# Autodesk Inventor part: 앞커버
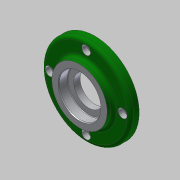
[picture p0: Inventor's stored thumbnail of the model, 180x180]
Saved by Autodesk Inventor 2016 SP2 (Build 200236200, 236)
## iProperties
Created: 2019-01
Part Number: 앞커버
Material: 알루미늄 6061
Document SubType Name: Modeling
Designer: mduedu
Density: 1 g/cm^3
Appearance: 알루미늄 - 평지
Author: mduedu
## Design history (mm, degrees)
sketch "스케치1"
  geometry: L1 (0, 0)-(6, 0); L2 (6, 0)-(6, 25); L3 (6, 25)-(0, 25); L4 (0, 25)-(0, 0); L5 (6, 0)-(14, 0); L6 (14, 0)-(14, 40); L7 (14, 40)-(6, 40); L8 (6, 40)-(6, 0); L9 (14, 0)-(19, 0); L10 (19, 0)-(19, 26); L11 (19, 26)-(14, 26); L12 (14, 26)-(14, 0)
  constraints: 24 end point, 6 parallel, 3 horizontal, 3 perpendicular
  dimensions: "d6" = 80 diameter of L7 L5; "d8" = 50 diameter of L3 L1; "d9" = 52 diameter of L11 L9; "d10" = 5 distance of L10.end L11.end; "d11" = 6 distance of L2.end L3.end; "d12" = 19 distance between parallel lines of L4 L10; "d13" = 8 distance of L6.end L7.end (derived)
revolve "회전1" sketch "스케치1" stored, may be unused: angle "d5" = 90 deg
sketch "스케치2"
  geometry: C1 r 13.5 at (0, 0); 1 further point
  constraints: 1 centre point, 1 coincident
  dimensions: "d14" = 27 diameter of C1
extrude "돌출1" cut sketch "스케치2" stored distance "d15" = 10; taper "d16" = 0 deg
sketch "스케치3" dims "d17" = 66
  geometry: 6 further points
  constraints: 2 vertical alignment, 1 coincident, 7 other
  dimensions: "d20" = 360 deg dimension on point (0, 0) point (0, 33) (derived)
sketch "스케치4"
  geometry: 4 further points
  constraints: 4 other
hole "구멍1" sketch "스케치4" at (-33, 0), (0, -33), (33, 0), (0, 33) diameter "d22" = 4.5; stored, may be unused: countersink angle "d26" = 90 deg, drill point angle "d28" = 0 deg; dims "d23" = 6, "d24" = 8, "d25" = 4.6, "d27" = 8
fillet "모깎기1" dims "d29" = 3
sketch "스케치5"
  geometry: C1 r 19 at (0, 0); 1 further point
  constraints: 1 centre point, 1 coincident
  dimensions: "d30" = 38 diameter of C1
extrude "돌출2" cut sketch "스케치5" distance "d31" = 8.3; taper "d32" = 0 deg
fillet "모깎기2" dims "d33" = 3
chamfer "모따기1" distance "d34" = 0.8; stored, may be unused: second distance "d35" = 2, angle "d36" = 30 deg
fillet "모깎기3" dims "d37" = 0.5
sketch "스케치6"
  geometry: C1 r 22 at (0, 0); 1 further point
  constraints: 1 centre point, 1 coincident
  dimensions: "d38" = 44 diameter of C1
extrude "돌출3" cut sketch "스케치6" distance "d39" = 5; taper "d40" = 0 deg
fillet "모깎기4" dims "d41" = 3
chamfer "모따기2" distance "d42" = 1; stored, may be unused: second distance "d43" = 2, angle "d44" = 30 deg
node "솔리드1"
